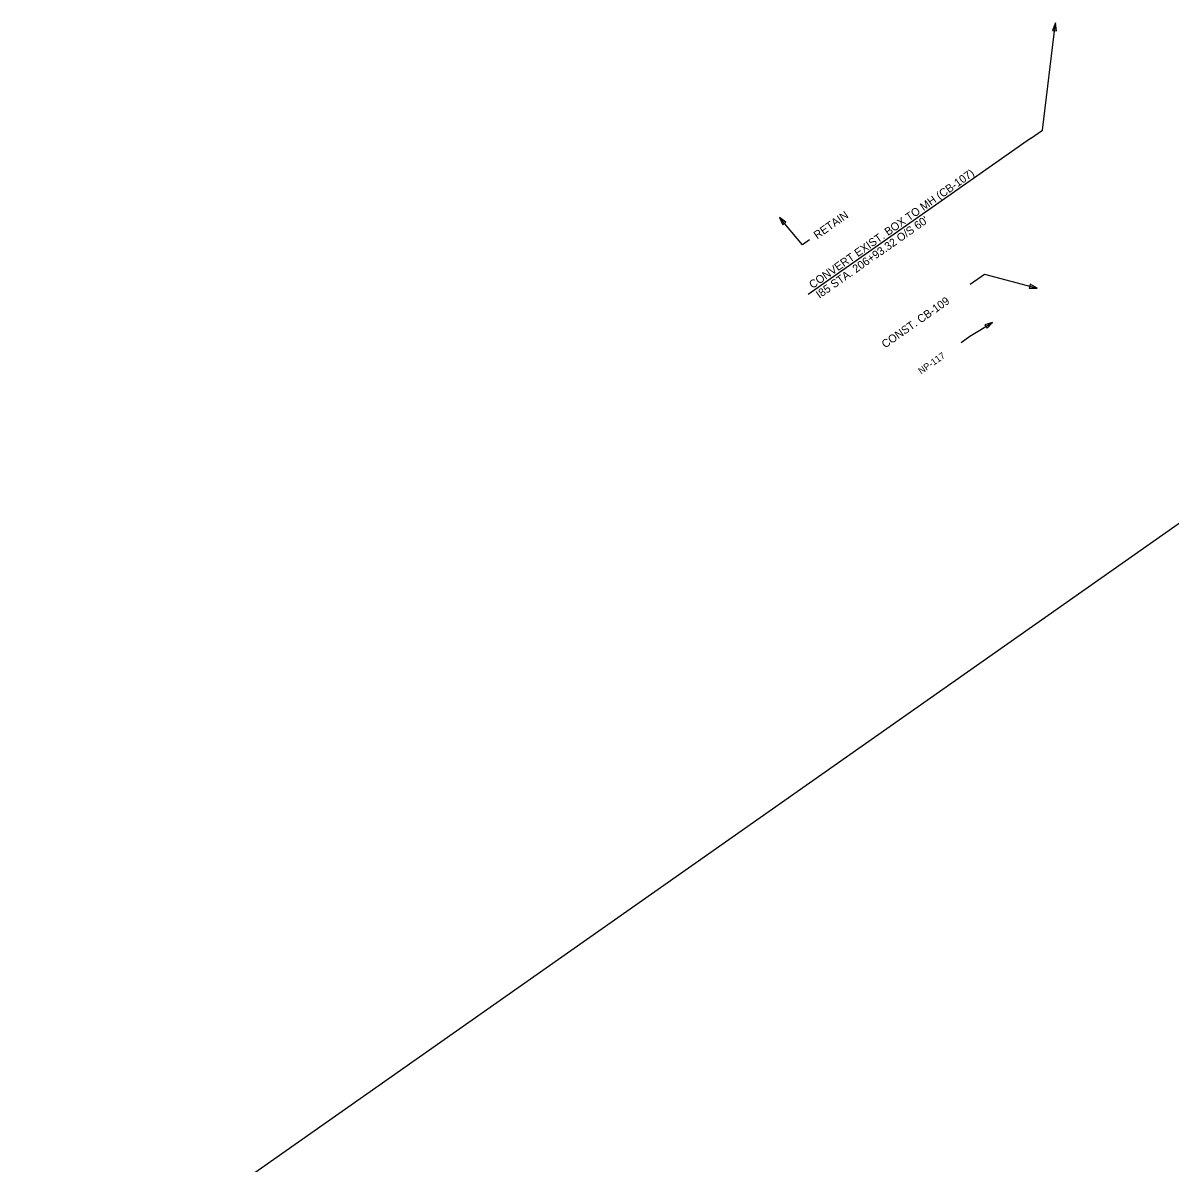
# Model space of a CAD drawing. Extents: x 1602342 to 1604404, y 1087462 to 1090274.
# Drawn here: x 1602639 to 1603498, y 1088812 to 1089666 of the extents above; entities that cross this region are included whole.
import ezdxf

# ---------------------------------------------------------------- set-up
doc = ezdxf.new("R2010")
doc.units = 0
doc.layers.add('Plan_Clip', color=7, linetype='Continuous')
doc.layers.add('RD_TX_Drainage', color=7, linetype='Continuous')

msp = doc.modelspace()

# ---------------------------------------------------------------- linework, layer by layer
at = {"layer": 'Plan_Clip'}
msp.add_lwpolyline([(1604005.53, 1089249.68), (1604177.81, 1089004.07), (1604362.43, 1088735.18), (1603082.39, 1087856.27), (1602843.15, 1088301.48), (1602638.5, 1088682.3), (1603690.27, 1089421.2), (1603708.44, 1089395.33), (1603838.88, 1089486.97)], close=True, dxfattribs=at)
msp.add_lwpolyline([(1604005.53, 1089249.68), (1604177.81, 1089004.07), (1604362.43, 1088735.18), (1603082.39, 1087856.27), (1602843.15, 1088301.48), (1602638.5, 1088682.3), (1603690.27, 1089421.2), (1603708.44, 1089395.33), (1603838.88, 1089486.97)], close=True, dxfattribs=at)
msp.add_lwpolyline([(1604005.53, 1089249.68), (1604177.81, 1089004.07), (1604362.43, 1088735.18), (1603082.39, 1087856.27), (1602843.15, 1088301.48), (1602638.5, 1088682.3), (1603690.27, 1089421.2), (1603708.44, 1089395.33), (1603838.88, 1089486.97)], close=True, dxfattribs=at)
msp.add_lwpolyline([(1604005.53, 1089249.68), (1604177.81, 1089004.07), (1604362.43, 1088735.18), (1603082.39, 1087856.27), (1602843.15, 1088301.48), (1602638.5, 1088682.3), (1603690.27, 1089421.2), (1603708.44, 1089395.33), (1603838.88, 1089486.97)], close=True, dxfattribs=at)
msp.add_lwpolyline([(1604005.53, 1089249.68), (1604177.81, 1089004.07), (1604362.43, 1088735.18), (1603082.39, 1087856.27), (1602843.15, 1088301.48), (1602638.5, 1088682.3), (1603690.27, 1089421.2), (1603708.44, 1089395.33), (1603838.88, 1089486.97)], close=True, dxfattribs=at)
at = {"layer": 'RD_TX_Drainage'}
msp.add_line((1603393.79, 1089579.5), (1603227.22, 1089462.66), dxfattribs=at)
for points in [[(1603393.79, 1089579.5), (1603402.84, 1089585.85), (1603412.54, 1089666.24)], [(1603228.06, 1089503.52), (1603222.99, 1089499.96), (1603205.57, 1089520.3)], [(1603348.56, 1089470.52), (1603359.22, 1089478), (1603398.83, 1089467.47)], [(1603341.72, 1089426.66), (1603348.42, 1089431.36), (1603365.36, 1089441.63)]]:
    msp.add_lwpolyline(points, dxfattribs=at)
for points in [[(1603413.39, 1089660.3), (1603412.54, 1089666.24), (1603410.31, 1089660.67)], [(1603210.52, 1089516.91), (1603205.57, 1089520.3), (1603208.16, 1089514.89)], [(1603392.83, 1089467.46), (1603398.83, 1089467.47), (1603393.63, 1089470.46)], [(1603361.21, 1089437.3), (1603365.36, 1089441.63), (1603359.6, 1089439.96)]]:
    msp.add_lwpolyline(points, close=True, dxfattribs=at)

# ---------------------------------------------------------------- texts
for s, height, p in [('CONVERT EXIST. BOX TO MH (CB-107)', 6, (1603230.45, 1089466.76)), ('RETAIN', 6, (1603233.88, 1089503.93)), ("I85 STA. 206+93.32 O/S 60'", 6, (1603235.62, 1089459.39)), ('CONST. CB-109', 6, (1603284.84, 1089422.16)), ('NP-117', 5, (1603311.83, 1089402.64))]:
    msp.add_text(s, height=height, rotation=35.04683, dxfattribs=at).set_placement(p)

doc.saveas('drawing.dxf')
